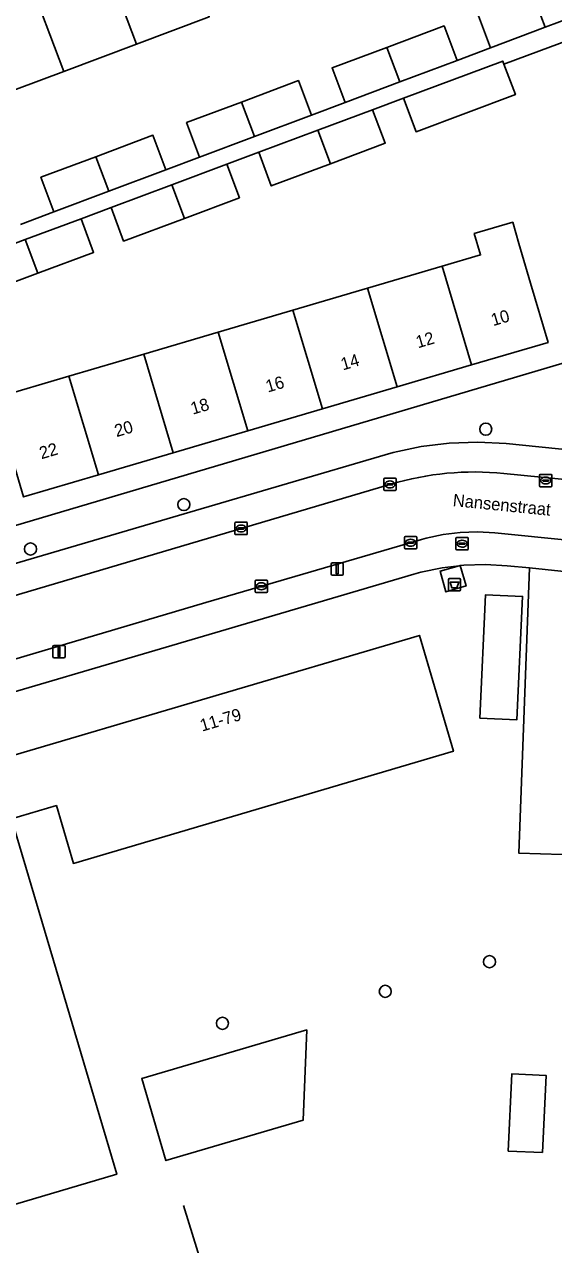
# Model space of a CAD drawing. Extents: x 161248 to 161848, y 384871 to 385383.
# Drawn here: x 161547.1 to 161590, y 384947.9 to 385046.9 of the extents above; entities that cross this region are included whole.
import ezdxf

# ---------------------------------------------------------------- set-up
doc = ezdxf.new("R2010")
doc.units = 0
for name, color, linetype in [('IMGEO_Afval_apart_plaats', 7, 'Continuous'), ('IMGEO_Boom', 7, 'Continuous'), ('IMGEO_Brandkraan', 7, 'Continuous'), ('IMGEO_Erf', 7, 'Continuous'), ('IMGEO_Groenvoorziening', 7, 'Continuous'), ('IMGEO_Kolk', 7, 'Continuous'), ('IMGEO_Lichtmast', 7, 'Continuous'), ('IMGEO_Muur', 7, 'Continuous'), ('IMGEO_Openbare_ruimte_label', 7, 'Continuous'), ('IMGEO_Pand', 7, 'Continuous'), ('IMGEO_Pand_nummerreeks', 7, 'Continuous'), ('IMGEO_Parkeervlak_open', 7, 'Continuous'), ('IMGEO_Rijbaan_lokaal_open', 7, 'Continuous'), ('IMGEO_Rioolput', 7, 'Continuous'), ('IMGEO_Voetpad_gesloten', 7, 'Continuous'), ('IMGEO_Voetpad_open', 7, 'Continuous')]:
    doc.layers.add(name, color=color, linetype=linetype)

msp = doc.modelspace()

# ---------------------------------------------------------------- linework, layer by layer
at = {"layer": 'IMGEO_Afval_apart_plaats'}
for p, q in [((161581.486, 385001.045), (161581.486, 385001.845)), ((161581.486, 385001.845), (161581.486, 385001.045)), ((161581.586, 385001.945), (161582.376, 385001.945)), ((161582.376, 385001.945), (161581.586, 385001.945)), ((161582.476, 385001.845), (161582.476, 385001.045)), ((161582.476, 385001.045), (161582.476, 385001.845)), ((161582.376, 385000.945), (161581.586, 385000.945)), ((161581.586, 385000.945), (161582.376, 385000.945))]:
    msp.add_line(p, q, dxfattribs=at)
msp.add_lwpolyline([(161581.629, 385001.659), (161582.333, 385001.659), (161582.184, 385001.189), (161581.778, 385001.189), (161581.629, 385001.659)], dxfattribs=at)
for centre, start, end in [((161581.586, 385001.845), 90, 180), ((161581.586, 385001.845), 90, 180), ((161582.376, 385001.845), 0, 90), ((161582.376, 385001.845), 360, 90), ((161581.586, 385001.045), 180, 270), ((161581.586, 385001.045), 180, 270), ((161582.376, 385001.045), 270, 0), ((161582.376, 385001.045), 270, 0)]:
    msp.add_arc(centre, 0.1, start, end, dxfattribs=at)
at = {"layer": 'IMGEO_Boom'}
for centre in [(161584.517, 385014.058), (161560.031, 385007.942), (161547.592, 385004.341), (161584.823, 384970.871), (161576.368, 384968.464), (161563.162, 384965.872)]:
    msp.add_circle(centre, 0.489, dxfattribs=at)
at = {"layer": 'IMGEO_Brandkraan'}
for p, q in [((161582.1, 385004.347), (161582.1, 385005.199)), ((161582.175, 385005.273), (161583.027, 385005.273)), ((161583.101, 385005.199), (161583.101, 385004.347)), ((161583.027, 385004.273), (161582.175, 385004.273)), ((161582.359, 385004.767), (161582.359, 385004.779)), ((161582.797, 385004.73), (161582.399, 385004.73)), ((161582.402, 385004.816), (161582.8, 385004.816)), ((161582.611, 385004.493), (161582.586, 385004.493)), ((161582.588, 385005.053), (161582.613, 385005.053)), ((161582.843, 385004.779), (161582.843, 385004.767))]:
    msp.add_line(p, q, dxfattribs=at)
for points in [[(161582.1, 385004.347), (161582.1, 385005.199)], [(161582.175, 385005.273), (161583.027, 385005.273)], [(161583.101, 385005.199), (161583.101, 385004.347)], [(161583.027, 385004.273), (161582.175, 385004.273)]]:
    msp.add_lwpolyline(points, dxfattribs=at)
for centre, radius, start, end in [((161582.177, 385005.197), 0.0765, 91.55205, 178.44795), ((161582.177, 385005.197), 0.0765, 91.55205, 178.44795), ((161583.025, 385005.197), 0.0765, 1.55205, 88.44795), ((161583.025, 385005.197), 0.0765, 1.55205, 88.44795), ((161582.177, 385004.349), 0.0765, 181.55205, 268.44795), ((161582.177, 385004.349), 0.0765, 181.55205, 268.44795), ((161582.399, 385004.776), 0.0403, 85.87752, 175.75265), ((161582.396, 385004.766), 0.0366, 178.93798, 274.71019), ((161582.8, 385004.773), 0.043, 264.86636, 352.45326), ((161582.804, 385004.778), 0.0386, 1.73085, 96.63898), ((161583.025, 385004.349), 0.0765, 271.55205, 358.44795), ((161583.025, 385004.349), 0.0765, 271.55205, 358.44795)]:
    msp.add_arc(centre, radius, start, end, dxfattribs=at)
for centre, major_axis, ratio, start_param, end_param in [((161582.587, 385004.773), (-0.387, 0.002), 0.722429, 4.712389, 7.853982), ((161582.612, 385004.773), (-0.39, 0.002), 0.717154, 1.570796, 4.712389)]:
    msp.add_ellipse(centre, major_axis=major_axis, ratio=ratio, start_param=start_param, end_param=end_param, dxfattribs=at)
at = {"layer": 'IMGEO_Erf'}
for points in [[(161546.78, 385030.661), (161549.498, 385031.681), (161548.444, 385034.487), (161552.888, 385036.156), (161557.523, 385037.897), (161558.577, 385035.092), (161561.305, 385036.117), (161560.251, 385038.923), (161564.696, 385040.593), (161569.33, 385042.333), (161570.384, 385039.528), (161573.111, 385040.552), (161572.057, 385043.358), (161576.501, 385045.027), (161581.136, 385046.768), (161582.19, 385043.963), (161584.899, 385044.98), (161583.845, 385047.786)], [(161562.095, 385047.515), (161556.182, 385045.294), (161550.288, 385043.079), (161544.394, 385040.865)], [(161593.334, 385046.385), (161585.993, 385043.661), (161586.916, 385041.192), (161578.862, 385038.18), (161577.843, 385040.903), (161575.344, 385039.969), (161576.363, 385037.245), (161571.921, 385035.584), (161567.119, 385033.787), (161566.1, 385036.512), (161563.522, 385035.548), (161564.541, 385032.823), (161560.086, 385031.157), (161555.15, 385029.31), (161554.131, 385032.035), (161551.693, 385031.123), (161552.712, 385028.399), (161548.194, 385026.709), (161543.541, 385024.969)], [(161544.637, 385016.561), (161550.695, 385018.346), (161556.791, 385020.143), (161562.811, 385021.917), (161568.86, 385023.7), (161574.928, 385025.488), (161580.977, 385027.271), (161584.095, 385028.19), (161583.585, 385029.921), (161586.7, 385030.839), (161587.21, 385029.108), (161588.157, 385025.894), (161589.571, 385021.097), (161583.373, 385019.27), (161577.34, 385017.492), (161571.273, 385015.704), (161565.234, 385013.924), (161559.162, 385012.134), (161553.11, 385010.35), (161547.038, 385008.562)], [(161541.43, 385004.793), (161590.958, 385019.461)], [(161625.827, 384949.231), (161624.614, 384953.921), (161625.652, 384973.647), (161592.287, 384974.913), (161592.462, 384979.511), (161587.199, 384979.67), (161588.066, 385002.802), (161586.255, 385002.988), (161584.496, 385003.089), (161582.734, 385003.033), (161582.44, 385002.997), (161582.926, 385001.35), (161581.281, 385000.863), (161580.806, 385002.554), (161582.364, 385002.988), (161580.985, 385002.819), (161579.262, 385002.45), (161578.675, 385002.287), (161570.906, 385000), (161530.284, 384988.042), (161526.38, 384986.893)]]:
    msp.add_lwpolyline(points, dxfattribs=at)
for points in [[(161584.04, 384990.634), (161584.501, 385000.625), (161587.502, 385000.491), (161587.049, 384990.486)], [(161551.077, 384978.837), (161549.692, 384983.529), (161546.066, 384982.466), (161554.584, 384953.632), (161537.526, 384948.588), (161526.699, 384985.306), (161543.744, 384990.345), (161544.689, 384987.166), (161579.135, 384997.334), (161581.889, 384987.932)], [(161558.575, 384954.738), (161556.612, 384961.4), (161569.997, 384965.335), (161569.708, 384958.017)], [(161589.128, 384955.383), (161586.338, 384955.513), (161586.627, 384961.765), (161589.417, 384961.635)]]:
    msp.add_lwpolyline(points, close=True, dxfattribs=at)
at = {"layer": 'IMGEO_Groenvoorziening'}
msp.add_lwpolyline([(161588.066, 385002.802), (161587.199, 384979.67), (161592.462, 384979.511), (161593.647, 385002.23)], close=True, dxfattribs=at)
at = {"layer": 'IMGEO_Kolk'}
for p, q in [((161576.245, 385009.152), (161576.245, 385010.004)), ((161576.32, 385010.078), (161577.172, 385010.078)), ((161576.504, 385009.572), (161576.504, 385009.584)), ((161576.942, 385009.535), (161576.544, 385009.535)), ((161576.547, 385009.621), (161576.945, 385009.621)), ((161576.756, 385009.298), (161576.731, 385009.298)), ((161576.733, 385009.858), (161576.758, 385009.858)), ((161576.988, 385009.584), (161576.988, 385009.572)), ((161577.246, 385010.004), (161577.246, 385009.152)), ((161577.172, 385009.078), (161576.32, 385009.078)), ((161564.178, 385005.579), (161564.178, 385006.431)), ((161564.253, 385006.505), (161565.105, 385006.505)), ((161564.666, 385006.285), (161564.691, 385006.285)), ((161565.179, 385006.431), (161565.179, 385005.579)), ((161565.105, 385005.505), (161564.253, 385005.505)), ((161564.437, 385005.999), (161564.437, 385006.011)), ((161564.875, 385005.962), (161564.477, 385005.962)), ((161564.48, 385006.048), (161564.878, 385006.048)), ((161564.689, 385005.725), (161564.664, 385005.725)), ((161564.921, 385006.011), (161564.921, 385005.999)), ((161577.921, 385004.425), (161577.921, 385005.277)), ((161577.996, 385005.351), (161578.848, 385005.351)), ((161578.922, 385005.277), (161578.922, 385004.425)), ((161578.848, 385004.351), (161577.996, 385004.351)), ((161578.18, 385004.845), (161578.18, 385004.857)), ((161578.618, 385004.808), (161578.22, 385004.808)), ((161578.223, 385004.894), (161578.621, 385004.894)), ((161578.432, 385004.571), (161578.407, 385004.571)), ((161578.409, 385005.131), (161578.434, 385005.131)), ((161578.664, 385004.857), (161578.664, 385004.845)), ((161565.819, 385000.893), (161565.819, 385001.745)), ((161565.894, 385001.819), (161566.746, 385001.819)), ((161566.078, 385001.313), (161566.078, 385001.325)), ((161566.516, 385001.276), (161566.118, 385001.276)), ((161566.121, 385001.362), (161566.519, 385001.362)), ((161566.307, 385001.599), (161566.332, 385001.599)), ((161566.562, 385001.325), (161566.562, 385001.313)), ((161566.82, 385001.745), (161566.82, 385000.893)), ((161566.746, 385000.819), (161565.894, 385000.819)), ((161566.33, 385001.039), (161566.305, 385001.039))]:
    msp.add_line(p, q, dxfattribs=at)
for points in [[(161576.245, 385009.152), (161576.245, 385010.004)], [(161576.32, 385010.078), (161577.172, 385010.078)], [(161577.246, 385010.004), (161577.246, 385009.152)], [(161577.172, 385009.078), (161576.32, 385009.078)], [(161564.178, 385005.579), (161564.178, 385006.431)], [(161564.253, 385006.505), (161565.105, 385006.505)], [(161565.179, 385006.431), (161565.179, 385005.579)], [(161565.105, 385005.505), (161564.253, 385005.505)], [(161577.921, 385004.425), (161577.921, 385005.277)], [(161577.996, 385005.351), (161578.848, 385005.351)], [(161578.922, 385005.277), (161578.922, 385004.425)], [(161578.848, 385004.351), (161577.996, 385004.351)], [(161565.819, 385000.893), (161565.819, 385001.745)], [(161565.894, 385001.819), (161566.746, 385001.819)], [(161566.82, 385001.745), (161566.82, 385000.893)], [(161566.746, 385000.819), (161565.894, 385000.819)]]:
    msp.add_lwpolyline(points, dxfattribs=at)
for centre, radius, start, end in [((161576.322, 385010.002), 0.0765, 91.55205, 178.44795), ((161576.322, 385010.002), 0.0765, 91.55205, 178.44795), ((161576.322, 385009.154), 0.0765, 181.55205, 268.44795), ((161576.322, 385009.154), 0.0765, 181.55205, 268.44795), ((161576.544, 385009.581), 0.0403, 85.87752, 175.75265), ((161576.541, 385009.571), 0.0366, 178.93798, 274.71019), ((161576.945, 385009.578), 0.043, 264.86636, 352.45326), ((161576.949, 385009.583), 0.0386, 1.73085, 96.63898), ((161577.17, 385010.002), 0.0765, 1.55205, 88.44795), ((161577.17, 385010.002), 0.0765, 1.55205, 88.44795), ((161577.17, 385009.154), 0.0765, 271.55205, 358.44795), ((161577.17, 385009.154), 0.0765, 271.55205, 358.44795), ((161564.255, 385006.429), 0.0765, 91.55205, 178.44795), ((161564.255, 385006.429), 0.0765, 91.55205, 178.44795), ((161565.103, 385006.429), 0.0765, 1.55205, 88.44795), ((161565.103, 385006.429), 0.0765, 1.55205, 88.44795), ((161564.255, 385005.581), 0.0765, 181.55205, 268.44795), ((161564.255, 385005.581), 0.0765, 181.55205, 268.44795), ((161564.477, 385006.008), 0.0403, 85.87752, 175.75265), ((161564.474, 385005.998), 0.0366, 178.93798, 274.71019), ((161564.878, 385006.005), 0.043, 264.86636, 352.45326), ((161564.882, 385006.01), 0.0386, 1.73085, 96.63898), ((161565.103, 385005.581), 0.0765, 271.55205, 358.44795), ((161565.103, 385005.581), 0.0765, 271.55205, 358.44795), ((161577.998, 385005.275), 0.0765, 91.55205, 178.44795), ((161577.998, 385005.275), 0.0765, 91.55205, 178.44795), ((161578.846, 385005.275), 0.0765, 1.55205, 88.44795), ((161578.846, 385005.275), 0.0765, 1.55205, 88.44795), ((161577.998, 385004.427), 0.0765, 181.55205, 268.44795), ((161577.998, 385004.427), 0.0765, 181.55205, 268.44795), ((161578.22, 385004.854), 0.0403, 85.87752, 175.75265), ((161578.217, 385004.844), 0.0366, 178.93798, 274.71019), ((161578.621, 385004.851), 0.043, 264.86636, 352.45326), ((161578.625, 385004.856), 0.0386, 1.73085, 96.63898), ((161578.846, 385004.427), 0.0765, 271.55205, 358.44795), ((161578.846, 385004.427), 0.0765, 271.55205, 358.44795), ((161565.896, 385001.743), 0.0765, 91.55205, 178.44795), ((161565.896, 385001.743), 0.0765, 91.55205, 178.44795), ((161566.118, 385001.322), 0.0403, 85.87752, 175.75265), ((161566.115, 385001.312), 0.0366, 178.93798, 274.71019), ((161566.519, 385001.319), 0.043, 264.86636, 352.45326), ((161566.523, 385001.324), 0.0386, 1.73085, 96.63898), ((161566.744, 385001.743), 0.0765, 1.55205, 88.44795), ((161566.744, 385001.743), 0.0765, 1.55205, 88.44795), ((161565.896, 385000.895), 0.0765, 181.55205, 268.44795), ((161565.896, 385000.895), 0.0765, 181.55205, 268.44795), ((161566.744, 385000.895), 0.0765, 271.55205, 358.44795), ((161566.744, 385000.895), 0.0765, 271.55205, 358.44795)]:
    msp.add_arc(centre, radius, start, end, dxfattribs=at)
for centre, major_axis, ratio, start_param, end_param in [((161576.732, 385009.578), (-0.387, 0.002), 0.722429, 4.712389, 7.853982), ((161576.757, 385009.578), (-0.39, 0.002), 0.717154, 1.570796, 4.712389), ((161564.665, 385006.005), (-0.387, 0.002), 0.722429, 4.712389, 7.853982), ((161564.69, 385006.005), (-0.39, 0.002), 0.717154, 1.570796, 4.712389), ((161578.408, 385004.851), (-0.387, 0.002), 0.722429, 4.712389, 7.853982), ((161578.433, 385004.851), (-0.39, 0.002), 0.717154, 1.570796, 4.712389), ((161566.306, 385001.319), (-0.387, 0.002), 0.722429, 4.712389, 7.853982), ((161566.331, 385001.319), (-0.39, 0.002), 0.717154, 1.570796, 4.712389)]:
    msp.add_ellipse(centre, major_axis=major_axis, ratio=ratio, start_param=start_param, end_param=end_param, dxfattribs=at)
at = {"layer": 'IMGEO_Lichtmast'}
for p, q in [((161572.075, 385003.21), (161572.865, 385003.21)), ((161572.865, 385003.21), (161572.075, 385003.21)), ((161571.975, 385002.31), (161571.975, 385003.11)), ((161571.975, 385003.11), (161571.975, 385002.31)), ((161572.965, 385003.11), (161572.965, 385002.31)), ((161572.965, 385002.31), (161572.965, 385003.11)), ((161572.865, 385002.21), (161572.075, 385002.21)), ((161572.075, 385002.21), (161572.865, 385002.21)), ((161549.413, 384995.62), (161549.413, 384996.42)), ((161549.413, 384996.42), (161549.413, 384995.62)), ((161549.513, 384996.52), (161550.303, 384996.52)), ((161550.303, 384996.52), (161549.513, 384996.52)), ((161550.403, 384996.42), (161550.403, 384995.62)), ((161550.403, 384995.62), (161550.403, 384996.42)), ((161550.303, 384995.52), (161549.513, 384995.52)), ((161549.513, 384995.52), (161550.303, 384995.52))]:
    msp.add_line(p, q, dxfattribs=at)
for points in [[(161572.395, 385003.085), (161572.545, 385003.085), (161572.545, 385002.335), (161572.395, 385002.335), (161572.395, 385003.085)], [(161549.833, 384996.395), (161549.983, 384996.395), (161549.983, 384995.645), (161549.833, 384995.645), (161549.833, 384996.395)]]:
    msp.add_lwpolyline(points, dxfattribs=at)
for centre, start, end in [((161572.075, 385003.11), 90, 180), ((161572.075, 385003.11), 90, 180), ((161572.865, 385003.11), 0, 90), ((161572.865, 385003.11), 360, 90), ((161572.075, 385002.31), 180, 270), ((161572.075, 385002.31), 180, 270), ((161572.865, 385002.31), 270, 0), ((161572.865, 385002.31), 270, 0), ((161549.513, 384996.42), 90, 180), ((161549.513, 384996.42), 90, 180), ((161550.303, 384996.42), 0, 90), ((161550.303, 384996.42), 360, 90), ((161549.513, 384995.62), 180, 270), ((161549.513, 384995.62), 180, 270), ((161550.303, 384995.62), 270, 0), ((161550.303, 384995.62), 270, 0)]:
    msp.add_arc(centre, 0.1, start, end, dxfattribs=at)
at = {"layer": 'IMGEO_Muur'}
msp.add_lwpolyline([(161571.394, 384908.101), (161571.334, 384914.167), (161565.708, 384932.672), (161560.012, 384951.103)], dxfattribs=at)
at = {"layer": 'IMGEO_Pand'}
for points in [[(161559.16, 385055.326), (161553.247, 385053.104), (161556.182, 385045.294), (161562.095, 385047.515)], [(161550.288, 385043.079), (161556.182, 385045.294), (161553.247, 385053.104), (161547.354, 385050.891)], [(161544.394, 385040.865), (161550.288, 385043.079), (161547.354, 385050.891), (161541.46, 385048.676)], [(161589.343, 385046.65), (161593.978, 385048.391), (161592.924, 385051.196), (161588.289, 385049.455)], [(161588.289, 385049.455), (161583.845, 385047.786), (161584.899, 385044.98), (161589.343, 385046.65)], [(161582.19, 385043.963), (161581.136, 385046.768), (161576.501, 385045.027), (161577.555, 385042.222)], [(161572.057, 385043.358), (161573.111, 385040.552), (161577.555, 385042.222), (161576.501, 385045.027)], [(161585.993, 385043.661), (161585.898, 385043.916), (161577.843, 385040.903), (161578.862, 385038.18), (161586.916, 385041.192)], [(161570.384, 385039.528), (161569.33, 385042.333), (161564.696, 385040.593), (161565.75, 385037.787)], [(161560.251, 385038.923), (161561.305, 385036.117), (161565.75, 385037.787), (161564.696, 385040.593)], [(161575.344, 385039.969), (161570.897, 385038.306), (161571.921, 385035.584), (161576.363, 385037.245)], [(161558.577, 385035.092), (161557.523, 385037.897), (161552.888, 385036.156), (161553.942, 385033.351)], [(161570.897, 385038.306), (161566.1, 385036.512), (161567.119, 385033.787), (161571.921, 385035.584)], [(161548.444, 385034.487), (161549.498, 385031.681), (161553.942, 385033.351), (161552.888, 385036.156)], [(161563.522, 385035.548), (161559.062, 385033.879), (161560.086, 385031.157), (161564.541, 385032.823)], [(161559.062, 385033.879), (161554.131, 385032.035), (161555.15, 385029.31), (161560.086, 385031.157)], [(161551.693, 385031.123), (161547.17, 385029.431), (161548.194, 385026.709), (161552.712, 385028.399)], [(161580.977, 385027.271), (161583.373, 385019.27), (161589.571, 385021.097), (161588.157, 385025.894), (161587.21, 385029.108), (161586.7, 385030.839), (161583.585, 385029.921), (161584.095, 385028.19)], [(161547.17, 385029.431), (161542.523, 385027.693), (161542.573, 385027.56), (161543.541, 385024.969), (161548.194, 385026.709)], [(161580.977, 385027.271), (161574.928, 385025.488), (161577.34, 385017.492), (161583.373, 385019.27)], [(161571.273, 385015.704), (161577.34, 385017.492), (161574.928, 385025.488), (161568.86, 385023.7)], [(161565.234, 385013.924), (161571.273, 385015.704), (161568.86, 385023.7), (161562.811, 385021.917)], [(161562.811, 385021.917), (161556.791, 385020.143), (161559.162, 385012.134), (161565.234, 385013.924)], [(161556.791, 385020.143), (161550.695, 385018.346), (161553.11, 385010.35), (161559.162, 385012.134)], [(161550.695, 385018.346), (161544.637, 385016.561), (161547.038, 385008.562), (161553.11, 385010.35)], [(161587.502, 385000.491), (161584.501, 385000.625), (161584.04, 384990.634), (161587.049, 384990.486)], [(161546.066, 384982.466), (161549.692, 384983.529), (161551.077, 384978.837), (161581.889, 384987.932), (161579.135, 384997.334), (161544.689, 384987.166), (161543.744, 384990.345), (161526.699, 384985.306), (161537.526, 384948.588), (161554.584, 384953.632)], [(161569.997, 384965.335), (161556.612, 384961.4), (161558.575, 384954.738), (161569.708, 384958.017)], [(161589.128, 384955.383), (161589.417, 384961.635), (161586.627, 384961.765), (161586.338, 384955.513)]]:
    msp.add_lwpolyline(points, close=True, dxfattribs=at)
at = {"layer": 'IMGEO_Parkeervlak_open'}
for points in [[(161591.742, 385012.334), (161586.184, 385012.887), (161583.874, 385013.013), (161581.562, 385012.932), (161579.267, 385012.645), (161577.006, 385012.154), (161576.357, 385011.973), (161560.505, 385007.334), (161544.393, 385002.586)], [(161585.987, 385010.474), (161622.298, 385006.895)], [(161544.407, 385000), (161576.83, 385009.603)]]:
    msp.add_lwpolyline(points, dxfattribs=at)
msp.add_arc((161583.646, 384986.516), 24.072, 84.41881, 106.44827, dxfattribs=at)
at = {"layer": 'IMGEO_Rijbaan_lokaal_open'}
for points in [[(161579.302, 385005.109), (161579.681, 385005.214), (161581.055, 385005.513), (161582.451, 385005.688), (161583.856, 385005.737), (161585.261, 385005.661), (161641.51, 385000), (161644.123, 384999.737), (161644.15, 385000), (161644.619, 385004.674), (161623.732, 385006.774), (161622.69, 385006.856), (161622.298, 385006.895), (161585.987, 385010.474)], [(161576.83, 385009.603), (161544.407, 385000), (161541.648, 384999.183), (161531.372, 384996.139), (161523.482, 384993.851), (161525.218, 384989.124), (161542.1, 384994.163), (161561.812, 385000), (161579.302, 385005.109)]]:
    msp.add_lwpolyline(points, dxfattribs=at)
msp.add_arc((161583.646, 384986.516), 24.072, 84.41881, 106.44827, dxfattribs=at)
at = {"layer": 'IMGEO_Rioolput'}
for p, q in [((161588.878, 385009.468), (161588.878, 385010.32)), ((161588.953, 385010.394), (161589.805, 385010.394)), ((161589.366, 385010.174), (161589.391, 385010.174)), ((161589.879, 385010.32), (161589.879, 385009.468)), ((161589.805, 385009.394), (161588.953, 385009.394)), ((161589.137, 385009.888), (161589.137, 385009.9)), ((161589.575, 385009.851), (161589.177, 385009.851)), ((161589.18, 385009.937), (161589.578, 385009.937)), ((161589.389, 385009.614), (161589.364, 385009.614)), ((161589.621, 385009.9), (161589.621, 385009.888))]:
    msp.add_line(p, q, dxfattribs=at)
for points in [[(161588.878, 385009.468), (161588.878, 385010.32)], [(161588.953, 385010.394), (161589.805, 385010.394)], [(161589.879, 385010.32), (161589.879, 385009.468)], [(161589.805, 385009.394), (161588.953, 385009.394)]]:
    msp.add_lwpolyline(points, dxfattribs=at)
for centre, radius, start, end in [((161588.955, 385010.318), 0.0765, 91.55205, 178.44795), ((161588.955, 385010.318), 0.0765, 91.55205, 178.44795), ((161589.803, 385010.318), 0.0765, 1.55205, 88.44795), ((161589.803, 385010.318), 0.0765, 1.55205, 88.44795), ((161588.955, 385009.47), 0.0765, 181.55205, 268.44795), ((161588.955, 385009.47), 0.0765, 181.55205, 268.44795), ((161589.177, 385009.897), 0.0403, 85.87752, 175.75265), ((161589.174, 385009.887), 0.0366, 178.93798, 274.71019), ((161589.578, 385009.894), 0.043, 264.86636, 352.45326), ((161589.582, 385009.899), 0.0386, 1.73085, 96.63898), ((161589.803, 385009.47), 0.0765, 271.55205, 358.44795), ((161589.803, 385009.47), 0.0765, 271.55205, 358.44795)]:
    msp.add_arc(centre, radius, start, end, dxfattribs=at)
for centre, major_axis, ratio, start_param, end_param in [((161589.365, 385009.894), (-0.387, 0.002), 0.722429, 4.712389, 7.853982), ((161589.39, 385009.894), (-0.39, 0.002), 0.717154, 1.570796, 4.712389)]:
    msp.add_ellipse(centre, major_axis=major_axis, ratio=ratio, start_param=start_param, end_param=end_param, dxfattribs=at)
at = {"layer": 'IMGEO_Voetpad_gesloten'}
msp.add_lwpolyline([(161582.44, 385002.997), (161582.437, 385003.008), (161582.364, 385002.988), (161580.806, 385002.554), (161581.281, 385000.863), (161582.926, 385001.35)], close=True, dxfattribs=at)
at = {"layer": 'IMGEO_Voetpad_open'}
for points in [[(161593.978, 385048.391), (161589.343, 385046.65), (161584.899, 385044.98), (161582.19, 385043.963), (161577.555, 385042.222), (161573.111, 385040.552), (161570.384, 385039.528), (161565.75, 385037.787), (161561.305, 385036.117), (161558.577, 385035.092), (161553.942, 385033.351), (161549.498, 385031.681), (161546.78, 385030.661)], [(161542.523, 385027.693), (161547.17, 385029.431), (161551.693, 385031.123), (161554.131, 385032.035), (161559.062, 385033.879), (161563.522, 385035.548), (161566.1, 385036.512), (161570.897, 385038.306), (161575.344, 385039.969), (161577.843, 385040.903), (161585.898, 385043.916), (161585.993, 385043.661), (161593.334, 385046.385)], [(161590.958, 385019.461), (161541.43, 385004.793)], [(161544.393, 385002.586), (161560.505, 385007.334), (161576.357, 385011.973), (161577.006, 385012.154), (161579.267, 385012.645), (161581.562, 385012.932), (161583.874, 385013.013), (161586.184, 385012.887), (161591.742, 385012.334)], [(161641.51, 385000), (161585.261, 385005.661), (161583.856, 385005.737), (161582.451, 385005.688), (161581.055, 385005.513), (161579.681, 385005.214), (161579.302, 385005.109), (161561.812, 385000), (161542.1, 384994.163), (161525.218, 384989.124), (161526.38, 384986.893), (161530.284, 384988.042), (161570.906, 385000), (161578.675, 385002.287), (161579.262, 385002.45), (161580.985, 385002.819), (161582.364, 385002.988), (161582.437, 385003.008), (161582.44, 385002.997), (161582.734, 385003.033), (161584.496, 385003.089), (161586.255, 385002.988), (161588.066, 385002.802), (161593.647, 385002.23)]]:
    msp.add_lwpolyline(points, dxfattribs=at)

# ---------------------------------------------------------------- texts
at = {"layer": 'IMGEO_Openbare_ruimte_label'}
msp.add_text('Nansenstraat', height=1, rotation=354.31792, dxfattribs=at).set_placement((161581.811, 385007.826))
at = {"layer": 'IMGEO_Pand_nummerreeks'}
for s, rotation, p in [('10', 16.42252, (161585.111, 385022.41)), ('12', 16.42252, (161579.016, 385020.613)), ('14', 16.42252, (161572.929, 385018.82)), ('16', 16.42252, (161566.839, 385017.025)), ('18', 16.42252, (161560.753, 385015.231)), ('20', 16.42252, (161554.576, 385013.41)), ('22', 16.42252, (161548.481, 385011.613)), ('11-79', 16.44389, (161561.508, 384989.524))]:
    msp.add_text(s, height=1, rotation=rotation, dxfattribs=at).set_placement(p)

doc.saveas('drawing.dxf')
